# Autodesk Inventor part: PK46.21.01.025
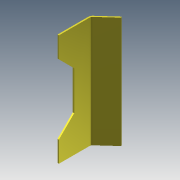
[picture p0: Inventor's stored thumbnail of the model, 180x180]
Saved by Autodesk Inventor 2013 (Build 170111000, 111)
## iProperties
Created: 2005-04
Part Number: PK46.21.01.025
Material: Steel, Mild
Document SubType Name: Sheet Metal
Designer: salex
Manufacturer: Standard
Standards Organization: Custom
Density: 7.86 g/cm^3
Sheet Metal Rule: Default
Author: salex
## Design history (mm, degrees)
node "ФлнОтгиб1"
sketch "Эскиз2"
  geometry: L1 (0, 223.327)-(0, 0); L2 (0, 0)-(800, 0); L3 (800, 0)-(800, 223.327); L4 (150, 0)-(260, 110); L5 (260, 110)-(540, 110); L6 (540, 110)-(650, 0); L7 (800, 221.178)-(0, 221.178) reference; L8 (0, 221.178)-(0, 0) reference; L9 (0, 0)-(800, 0) reference; L10 (800, 0)-(800, 221.178) reference
  constraints: 12 end point, 2 perpendicular, 2 point on line
  dimensions: "d11" = 110 distance between parallel lines of L5 L2; "d12" = 150 distance from line of L4.start L1; "d13" = 260 distance from line of L4.end L1; "d14" = 150 distance from line of L6.end L3 (= d12)
extrude "Выдавливание1" cut sketch "Эскиз2" stored distance "d15" = 10; taper "d16" = 0 deg
body "Solid1"
sketch "Эскиз1"
  geometry: L1 (-0.232, 229.772)-(114.768, 334.772); L2 (-0.232, 229.772)-(-0.232, -0.228)
  constraints: 4 end point, 1 vertical, 1 other
  dimensions: "d24" = 230 distance of L1.start L2.end; "d25" = 335 vertical distance of L2.end L1.end; "d26" = 115 horizontal distance of L1.start L1.end
feature "Плакирование1" dims "d4" = 800, "d5" = 10 (= BendReliefWidth), "d7" = 20 (= MinimumRemnant), "d9" = 20 (= BendRadius), "d10" = 10, "Thickness" = 10
feature "Изгиб1" dims "d5" = 10 (= BendReliefWidth), "d6" = 5 (= BendReliefDepth), "d7" = 20 (= MinimumRemnant), "d8" = 20 (= BendRadius), "d9" = 20 (= BendRadius), "d10" = 10, "SeamGap" = 0.01, "Thickness" = 10
other parameters: "BendRadius" = 20, "BendReliefDepth" = 5 (= 0.5 x Thickness), "d2" = 335, "d18" = 225, "d20" = 225
